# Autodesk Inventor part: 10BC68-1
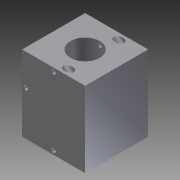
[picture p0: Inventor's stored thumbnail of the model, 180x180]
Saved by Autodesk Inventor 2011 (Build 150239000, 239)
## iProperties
Created: 2011-04
Part Number: 10BC68-1
Document SubType Name: Modeling
Designer: vadybininkas6
Density: 1 g/cm^3
Author: vadybininkas6
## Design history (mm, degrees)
feature "Base1"
body "Solid1"
